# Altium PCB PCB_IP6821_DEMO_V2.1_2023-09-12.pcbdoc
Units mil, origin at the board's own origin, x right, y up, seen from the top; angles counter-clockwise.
Board outline 2690 x 2170 mil, 2 copper layers (Top Layer, Bottom Layer); 35 components, 26 nets, 110 pads, 62 vias.
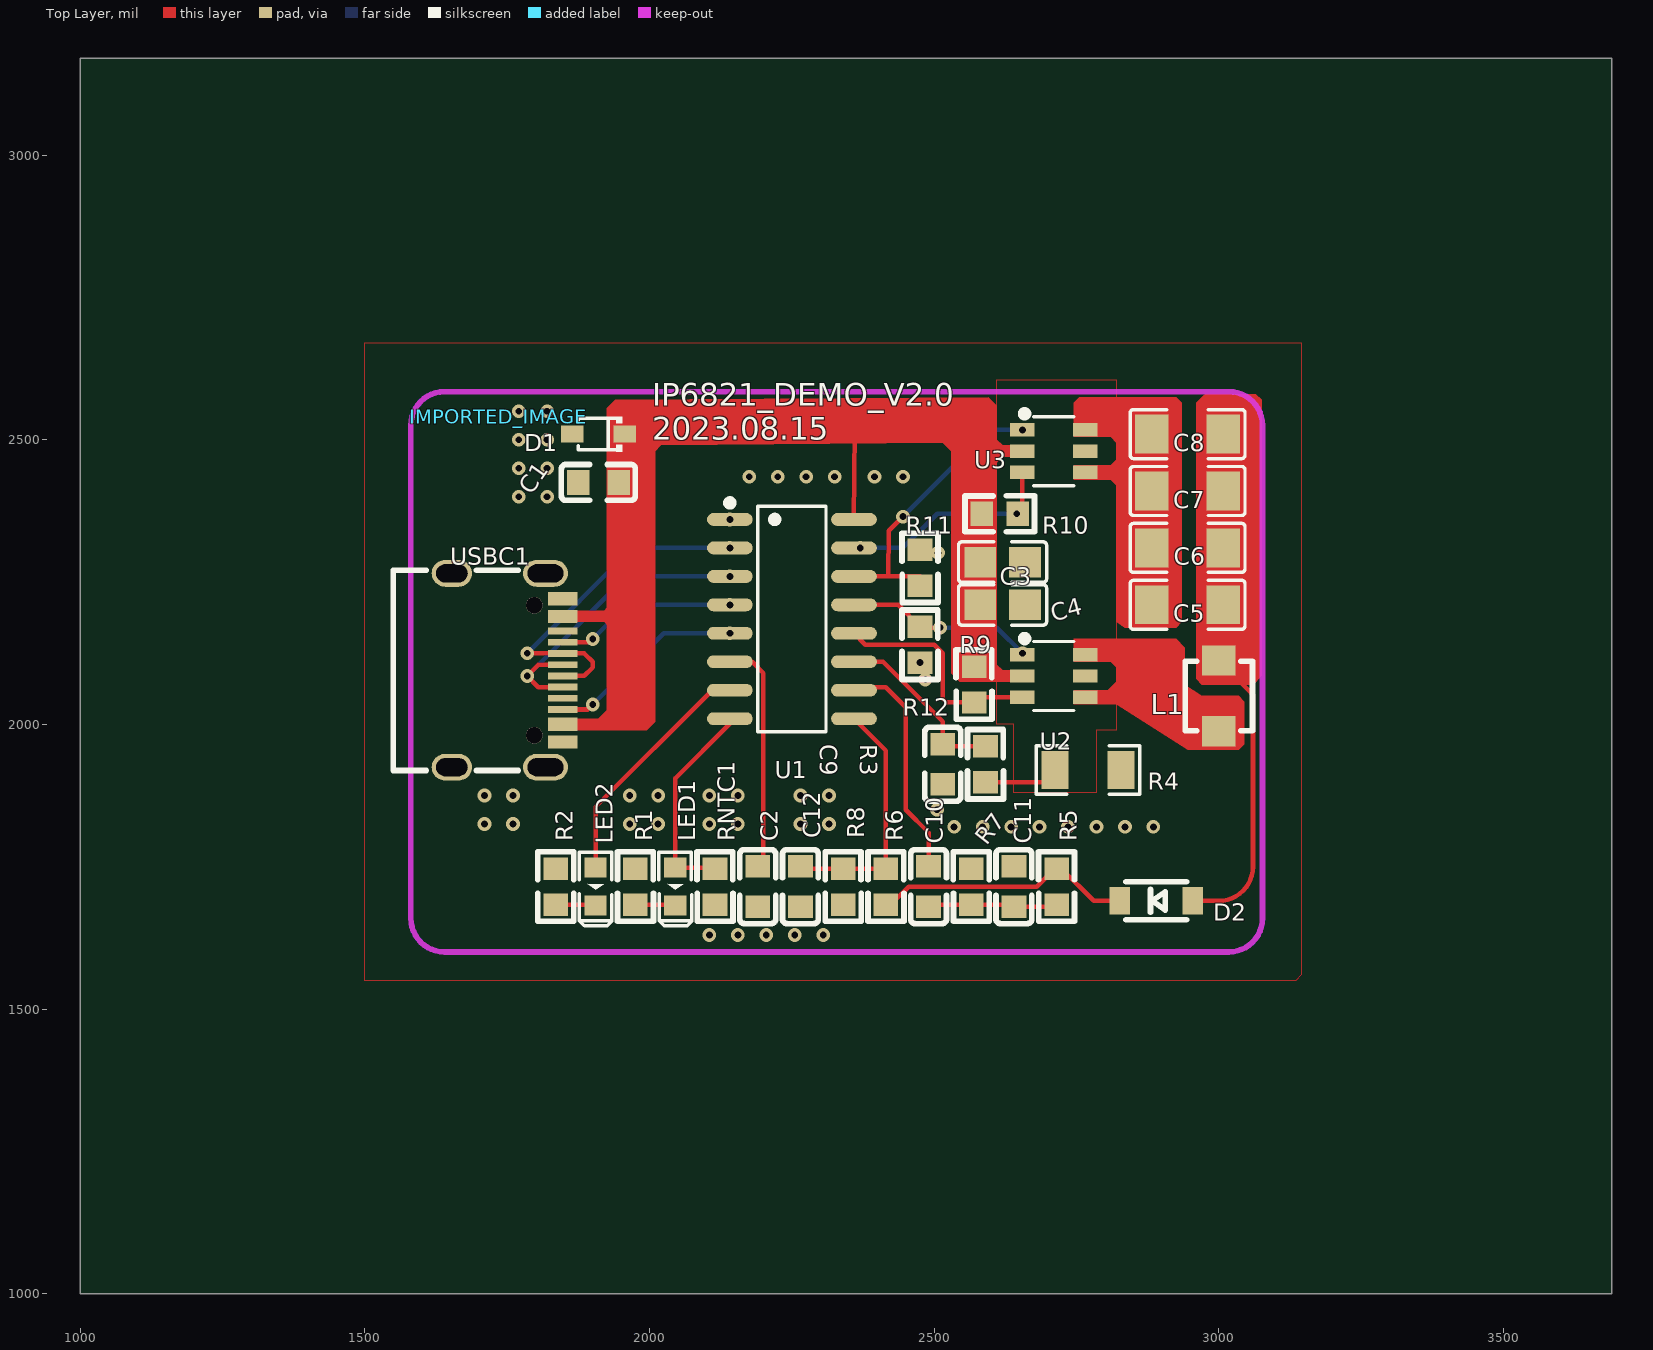
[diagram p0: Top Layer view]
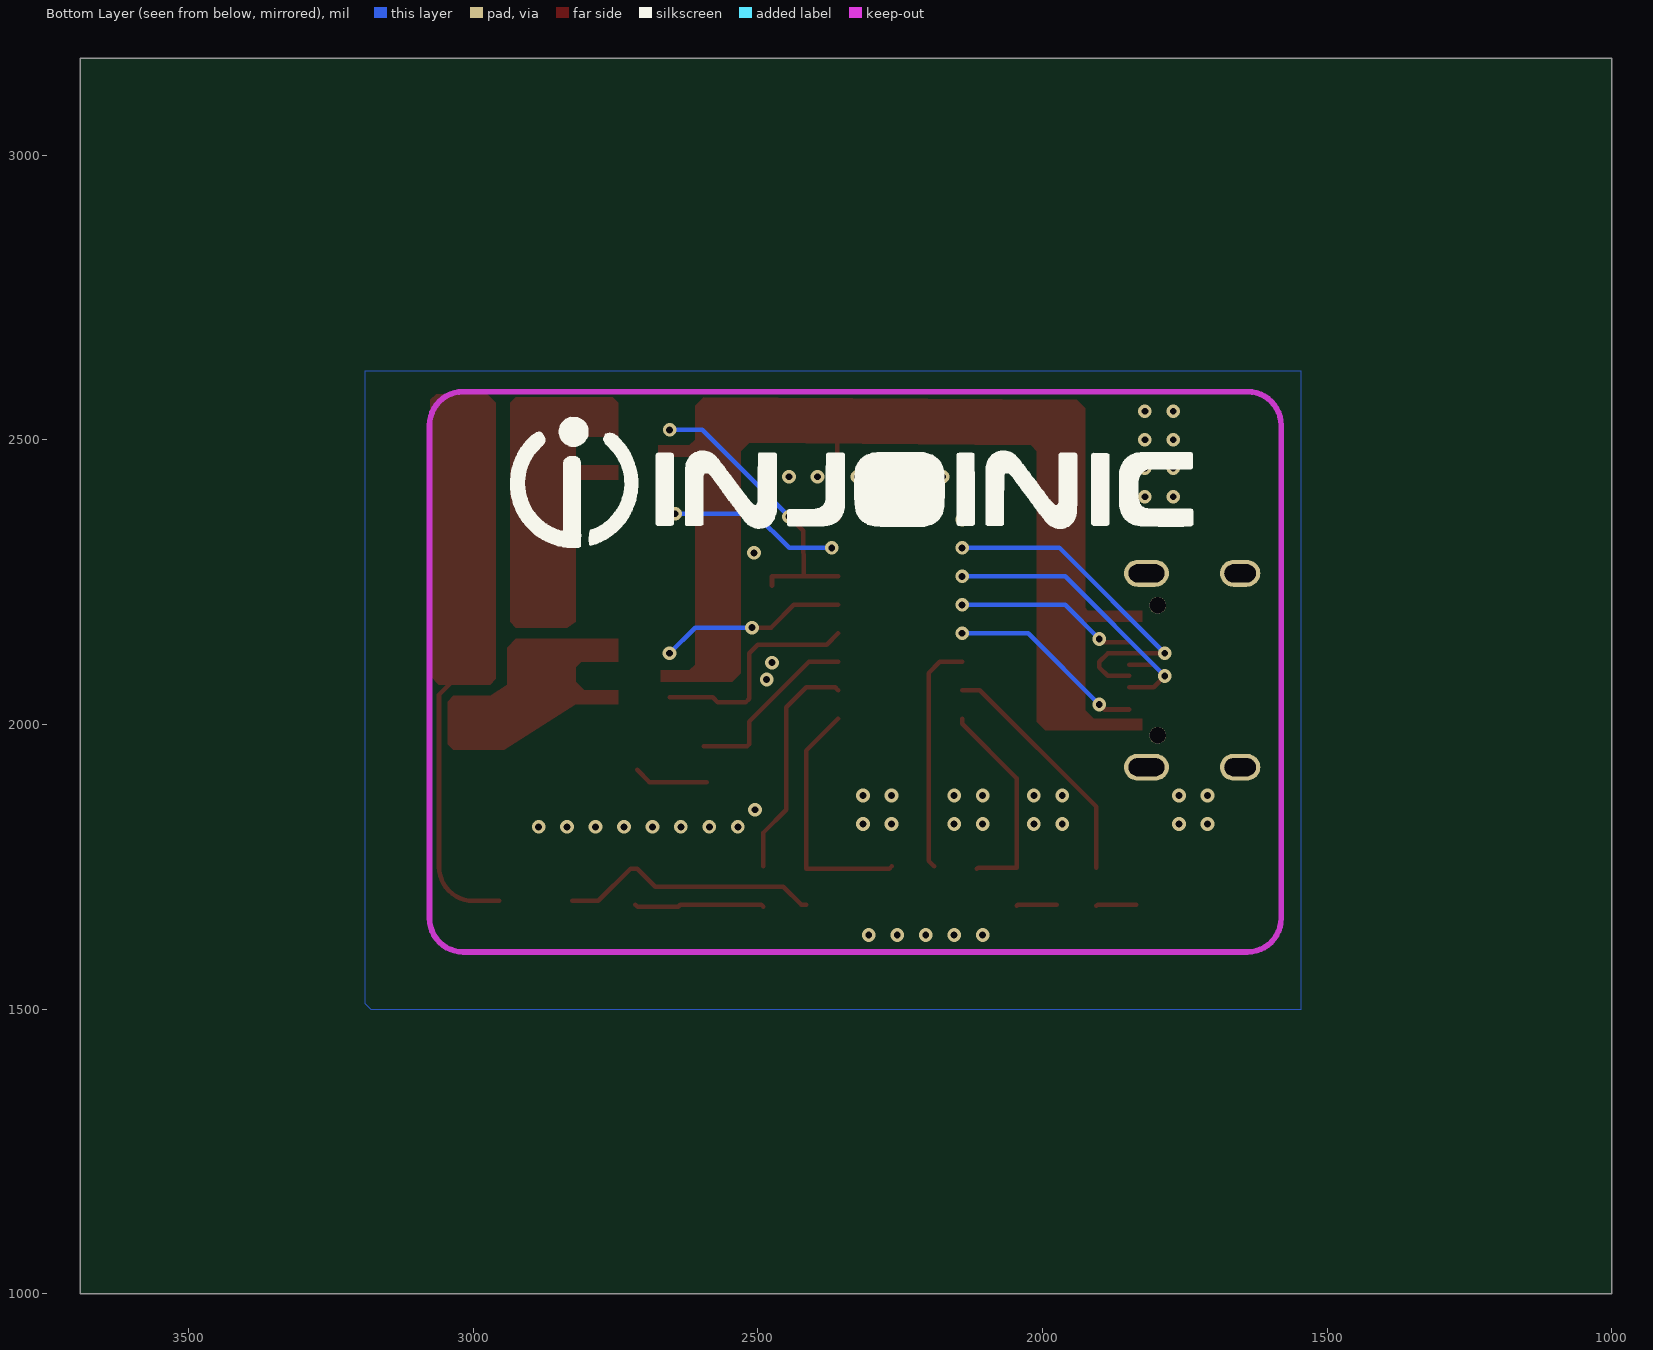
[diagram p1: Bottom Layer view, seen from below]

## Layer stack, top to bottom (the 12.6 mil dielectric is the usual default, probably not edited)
Top Layer: signal copper (thickness not stored)
Dielectric: dielectric 12.6, FR-4, Dk 4.8
Bottom Layer: signal copper (thickness not stored)

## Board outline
3690,1000 1000,1000 1000,3170 3690,3170

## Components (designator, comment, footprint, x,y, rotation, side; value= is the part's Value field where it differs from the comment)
C1 "10uF" C0603 1910,2425 r180 top
C2 "2.2uF" C0603 2190,1715 r90 top
C3 "22uF" C0805 2620,2285 r180 top
C4 "22uF" C0805 2620,2210 r180 top
C5 "100nF" C1206 2945,2210 r180 top
C6 "100nF" C1206 2945,2310 r180 top
C7 "100nF" C1206 2945,2410 r180 top
C8 "100nF" C1206 2945,2510 r180 top
C9 "10nF" C0603 2515.03,1930 r90 top
C10 "10nF" C0603 2490,1715 r270 top
C11 "10nF" C0603 2640,1715 r270 top
C12 "10nF" C0603 2265,1715 r90 top
D1 "BZT52-B14S" SOD-323_L1.9-W1.3-LS2.5-RD-1 1909.99,2510.04 r180 top
D2 "IN5819" SOD-123_L2.7-W1.6-LS3.7-R-RD 2890,1690 r0 top
IMPORTED_IMAGE "IMPORTED_IMAGE" IMPORTED_IMAGE 1735.09,2539.98 r0 top
L1 "6.3uH" IND-SMD_L4.5-W3.0 3000,2050 r90 top
LED1 "LED" LED0603_RED 2045,1715 r270 top
LED2 "LED" LED0603_GREEN 1905,1715 r270 top
R1 "1k" R0603 1975.03,1715 r270 top
R2 "1k" R0603 1835.03,1715 r270 top
R3 "3.3k" R0603 2590.03,1930 r90 top
R4 "20mR" R1206 2770,1920 r0 top
R5 "3.3k" R0603 2715.03,1715 r90 top
R6 "33k" R0603 2415.03,1715 r270 top
R7 "33k" R0603 2565.03,1715 r270 top
R8 "3.3k" R0603 2340.03,1715 r90 top
R9 "NC" R0603 2570,2070 r90 top
R10 "NC" R0603 2615,2370 r180 top
R11 "3.3k" R0603 2475,2275 r270 top
R12 "3.3k" R0603 2475,2140 r90 top
RNTC1 "100k" R0603 2115,1715 r90 top
U1 "IP6821" SOP-16_L9.9-W3.9-P1.27-LS6.0-BL 2250,2185 r270 top
U2 "AP8G02LI" SOT-23-6_L2.9-W1.6-P0.95-LS2.7-BL 2710,2085 r270 top
U3 "AP8G02LI" SOT-23-6_L2.9-W1.6-P0.95-LS2.7-BL 2710,2480 r270 top
USBC1 "TYPE-C-31-M-12" USB-C_SMD-TYPE-C-31-M-12 1749.99,2095.02 r270 top

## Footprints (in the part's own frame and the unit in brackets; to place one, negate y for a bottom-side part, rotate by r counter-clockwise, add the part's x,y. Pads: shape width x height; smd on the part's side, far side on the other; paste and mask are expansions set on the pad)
C0603 [mm]
  rect 1x1.1 smd paste+0 mask+0.102: 1(-0.9,0) 2(0.9,0)
  silkscreen extent -1.65,-0.8 1.65,0.8
C0805 [mm]
  rect 1.41x1.35 smd paste-100 mask+0.051: 1(-1,0) 2(1,0)
  silkscreen extent -1.96,-0.9 1.96,0.9
C1206 [mm]
  rect 1.485x1.728 smd paste-100 mask+0.051: 1(-1.593,0) 2(1.593,0)
  silkscreen extent -2.56,-1.09 2.56,1.09
IMPORTED_IMAGE [mil]
IND-SMD_L4.5-W3.0 [mm]
  rect 1.35x1.5 smd paste+0 mask+0.05: 1(-1.575,0) 2(1.575,0)
  silkscreen extent -1.55,-1.5 1.55,1.5
LED0603_GREEN [mm]
  rect 0.9x1 smd paste+0 mask+0.051: 1(-0.85,0) 2(0.85,0)
  silkscreen extent -1.54,-0.73 1.75,0.73
LED0603_RED [mm]
  rect 0.9x1 smd paste+0 mask+0.051: 1(-0.85,0) 2(0.85,0)
  silkscreen extent -1.54,-0.73 1.75,0.73
R0603 [mm]
  rect 1x1.1 smd paste+0 mask+0.102: 1(-0.8,0) 2(0.8,0)
  silkscreen extent -1.55,-0.8 1.55,0.81
R1206 [mil]
  rect 47.54x66.97 smd paste-3937.01 mask+2: 1(-58.22,0) 2(58.22,0)
  silkscreen extent -91,-42 91,42
SOD-123_L2.7-W1.6-LS3.7-R-RD [mil]
  rect 35.8x48 smd paste+0 mask+2: 1(64,0) 2(-64,0)
  silkscreen extent -53,-33 53,33
SOD-323_L1.9-W1.3-LS2.5-RD-1 [mm]
  rect 1x0.75 smd paste+0 mask+0.051: 1(-1.173,0) 2(1.173,0)
  silkscreen extent -1.05,-0.78 0.9,0.78
SOP-16_L9.9-W3.9-P1.27-LS6.0-BL [mil]
  oval 22.6x80.24 smd paste+0 mask+2: 1(-175,-109.02) 2(-125,-109.02) 3(-75,-109.02) 4(-25,-109.02) 5(25,-109.02) 6(75,-109.02) 7(125,-109.02) 8(175,-109.02) 9(175,109.02) 10(125,109.02) 11(75,109.02) 12(25,109.02) 13(-25,109.02) 14(-75,109.02) 15(-125,109.02) 16(-175,109.02)
  silkscreen extent -210,-115 198,60
SOT-23-6_L2.9-W1.6-P0.95-LS2.7-BL [mm]
  rect 0.6x1.1 smd paste+0 mask+0.051: 1(-0.95,-1.4) 2(0,-1.4) 3(0.95,-1.4) 4(0.95,1.4) 5(0,1.4) 6(-0.95,1.4)
  silkscreen extent -1.82,-1.45 1.54,0.89
USB-C_SMD-TYPE-C-31-M-12 [mm]
  oval 1.2x2 hole 0.8 slot 1.6 at 90 deg paste+0 mask+0.051: 0(-4.325,1.706) 1(4.325,1.706)
  oval 1.2x1.8 hole 0.8 slot 1.4 at 90 deg paste+0 mask+0.051: 2(4.325,-2.474) 3(-4.325,-2.474)
  rect 0.3x1.3 smd paste-100 mask+0.051: A1(-3.35,2.474) A4(-2.55,2.474) A5(-1.25,2.474) A6(-0.25,2.474) A7(0.25,2.474) A8(1.25,2.474) A9(2.55,2.474) A12(3.35,2.474) B1(3.05,2.474) B4(2.25,2.474) B5(1.75,2.474) B6(0.75,2.474) B7(-0.75,2.474) B8(-1.75,2.474) B9(-2.25,2.474) B12(-3.05,2.474)
  round 0.75 hole 0.75 unplated paste+0: ""(-2.9,1.206) ""(2.9,1.206)
  silkscreen extent -4.47,-5.09 4.47,0.49

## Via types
v1: diameter 24, hole 12, Top Layer to Bottom Layer, tented both sides, 62 vias

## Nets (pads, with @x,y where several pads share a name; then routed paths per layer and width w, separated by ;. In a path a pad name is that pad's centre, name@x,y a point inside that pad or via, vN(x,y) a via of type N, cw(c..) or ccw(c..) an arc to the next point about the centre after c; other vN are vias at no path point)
C7_2: C5.2 C6.2 C7.2 C8.2 U3.4 U3.6
CC1: U1.5 USBC1.B5 | length 349
  Top Layer w8: USBC1.B5 1891.1,2026.1 v1(1900,2035)
  Bottom Layer w8: v1(1900,2035) 2025,2160 v1(2140.98,2160)
CC2: U1.4 USBC1.A5 | length 320.8
  Top Layer w8: USBC1.A5 1894.23,2144.23 v1(1900,2150)
  Bottom Layer w8: v1(1900,2150) 1960,2210 v1(2140.98,2210)
D2_2: D2.2 R5.2 R6.2 | length 460.5
  Top Layer w8: R6.2 2423.5,1683.5 2455,1715 2680,1715 2711.5,1746.5 R5.2 2723.5,1746.5 2780,1690 D2.2
DM: U1.2 USBC1.A7 USBC1.B7 | length 622.4
  Top Layer w8: v1(1785,2125) USBC1.B7 1885.4,2124.6 1900,2110 1900,2100 1885.2,2085.2 USBC1.A7
  Bottom Layer w8: v1(1785,2125) 1970,2310 v1(2140.98,2310)
DP: U1.3 USBC1.A6 USBC1.B6 | length 569.6
  Top Layer w8: USBC1.B6 1804.51,2065.49 v1(1785,2085) 1804.86,2104.86 USBC1.A6
  Bottom Layer w8: v1(1785,2085) 1960,2260 v1(2140.98,2260)
DRV1H: R9.1 U1.12 U2.3 | length 396.8
  Top Layer w8: U1.12 2379.02,2140 2500,2140 2515,2125 2515,2045 2521.5,2038.5 R9.1 2579.1,2047.6 U2.3
DRV1L: R12.2 U1.13 U2.1 | length 331.2
  Top Layer w8: U1.13 2436.49,2210 R12.2 2476.49,2170 v1(2510,2170)
  Bottom Layer w8: v1(2510,2170) 2610,2170 v1(2655,2125)
DRV2H: R10.1 U1.15 U3.3 | length 375.9
  Top Layer w8: R10.1 2654.88,2378.38 U3.3
  Bottom Layer w8: v1(2370,2310) 2445,2310 2505,2370 v1(2645,2370)
DRV2L: R11.2 U1.14 U3.1 | length 520.9
  Top Layer w8: U1.14 2475,2260 R11.2 ; 2419.5,2260 2420,2340 v1(2445,2365)
  Bottom Layer w8: v1(2445,2365) 2597.4,2517.4 v1(2654.88,2517.4)
GND: C1.2 C2.1 C9.1 C11.1 C12.1 D1.2 R1.1 R2.1 R4.2 R7.1 R8.1 R11.1 R12.1 RNTC1.1 U1.1 USBC1.0 USBC1.1 USBC1.2 USBC1.3 USBC1.A1 USBC1.A12 USBC1.B1 USBC1.B12
  other v1: 2105,1630 2155,1630 2205,1630 2255,1630 2305,1630 2535,1820 2585,1820 2635,1820 2685,1820 2735,1820 2785,1820 2835,1820 2885,1820 1710,1825 1760,1825 1965,1825 2015,1825 2105,1825 2155,1825 2265,1825 2315,1825 2505,1850 1710,1875 1760,1875 1965,1875 2015,1875 2105,1875 2155,1875 2265,1875 2315,1875 2484.42,2078.98 2475,2108.5 2506.5,2301.26 2140.98,2360 1770,2400 1820,2400 2175,2435 2225,2435 2275,2435 2325,2435 2395,2435 2445,2435 1770,2450 1820,2450 1770,2500 1820,2500 1770,2550 1820,2550
ISNS: C9.2 R3.2 U1.11 | length 320.7
  Top Layer w8: U1.11 2410,2110 2515,2005 C9.2 ; C9.2 2518.94,1961.5 R3.2@2595,1961.5
L1_1: L1.1 U2.4 U2.6
LED1: LED1.1 RNTC1.2 U1.8 | length 372.1
  Top Layer w8: RNTC1.2 2113.03,1748.47 LED1.1 2045,1905 2140.98,2000.98 U1.8
LED2: LED2.1 U1.7 | length 427.4
  Top Layer w8: LED2.1 1905,1855 2110,2060 U1.7
PGND: C3.1 C4.1 R3.1 R4.1 U2.5 U3.5 | length 130.7
  Top Layer w8: R3.1 2690.29,1898.51 R4.1
R1_2: LED1.2 R1.2 | length 70.8
  Top Layer w8: R1.2 2043.03,1683.51 LED1.2
R2_2: LED2.2 R2.2 | length 70.8
  Top Layer w8: R2.2 1903.03,1683.51 LED2.2
R5_1: C10.2 C11.2 R5.1 R7.2 | length 229.9
  Top Layer w8: C10.2 2493.94,1683.5 R7.2 2636.06,1683.5 C11.2 2711.05,1679.56 R5.1
USBC1_A8: USBC1.A8
USBC1_B8: USBC1.B8
VBUS: C1.1 C3.2 C4.2 D1.1 R9.2 R10.2 U1.16 U2.2 U3.2 USBC1.A4 USBC1.A9 USBC1.B4 USBC1.B9 | length 155
  Top Layer w8: U1.16 2360,2515
VC: C5.1 C6.1 C7.1 C8.1 D2.1 L1.2 | length 527.1
  Top Layer w8: D2.1 2990,1690 3000,1690 ccw(c3000,1750) 3060,1750 3060,2052 L1.2
VCC: C2.2 U1.6 | length 411
  Top Layer w8: U1.6 2180,2110 2200,2090 2200,1760.43 C2.2
VCOIL: C12.2 R6.1 R8.2 U1.9 | length 438.3
  Top Layer w8: C12.2 2268.94,1746.5 R8.2 R6.1 2415,1954.02 U1.9
VDEM: C10.1 U1.10 | length 403.7
  Top Layer w8: U1.10 2364,2065 2415,2065 2450,2030 2450,1850 2490,1810 C10.1
pads on no net: USBC1.

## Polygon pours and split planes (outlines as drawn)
GND on Bottom Layer (solid): 1545,2620 3190,2620 3190,1510 3180,1500 1545,1500 1545,2620
PGND on Top Layer (solid): 2610,2605 2820,2605 2820,1990 2785,1990 2785,1880 2640,1880 2640,2000 2610,2000 2610,2605
GND on Top Layer (solid): 1500,2670 3145,2670 3145,1560 3135,1550 1500,1550 1500,2670

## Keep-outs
Keep-Out Layer:
  lines w10: 1580.59,1659.33 ccw(c1639.64,1659.33) 1639.64,1600.27 ; 1580.59,2525.47 cw(c1639.64,2525.47) 1639.64,2584.52 ; 3017.59,1600.27 ccw(c3017.59,1659.33) 3076.65,1659.33 ; 3017.59,2584.52 cw(c3017.59,2525.47) 3076.65,2525.47

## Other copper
Top Layer:
  region net L1_1: 2945,1955 2820,2035 2745,2035 2745,2060 2805,2060 2820,2075 2820,2100 2810,2110 2745,2110 2745,2150 2925,2150 2940,2135 2940,2070 2970,2050 3035,2050 3045,2040 3045,1965 3035,1955 2945,1955
  region net VC: 2960,2565 2975,2580 3065,2580 3075,2570 3075,2085 3060,2070 3055,2070 2970,2070 2960,2080 2960,2565
  region net C7_2: 2835,2170 2820,2180 2820,2420 2810,2430 2745,2430 2745,2455 2810,2455 2820,2465 2820,2495 2810,2505 2745,2505 2745,2565 2755,2575 2925,2575 2935,2565 2935,2180 2925,2170 2835,2170
  region net VBUS: 1875,2200 1920,2200 1925,2205 1925,2555 1940,2570 2595,2575 2610,2560 2610,2500 2620,2490 2675,2490 2675,2470 2620,2470 2610,2460 2610,2105 2620,2095 2670,2095 2670,2075 2545,2075 2530,2090 2530,2480 2515,2495 2020,2490 2010,2480 2010,2005 1995,1990 1825,1990 1825,2010 1910,2010 1915,2015 1925,2025 1925,2175 1920,2180 1825,2180 1825,2200

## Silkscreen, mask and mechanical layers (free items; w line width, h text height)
Top Overlay:
  text "IP6821_DEMO_V2.0 / 2023.08.15" at 2005,2500 h40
